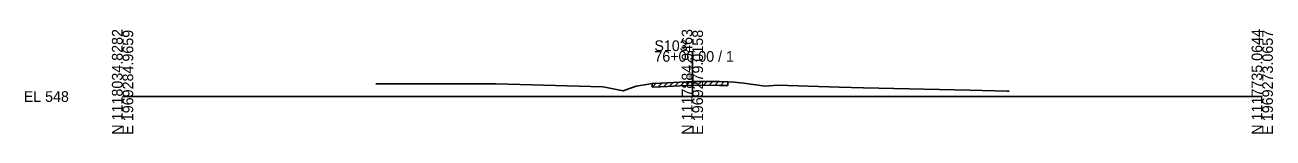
# Model space of a CAD drawing. Extents: x 974 to 1303, y 990 to 14518.
# Drawn here: x 974.3 to 1302.8, y 14490.3 to 14517.6 of the extents above; entities that cross this region are included whole.
import ezdxf

# ---------------------------------------------------------------- set-up
doc = ezdxf.new("R2010")
doc.units = 0
for name, color, linetype in [('Level 10', 7, 'Continuous'), ('Level 60', 7, 'Continuous'), ('Level 61', 7, 'Continuous'), ('Level 63', 7, 'Continuous')]:
    doc.layers.add(name, color=color, linetype=linetype)

msp = doc.modelspace()

# ---------------------------------------------------------------- linework, layer by layer
at = {"layer": 'Level 60'}
for p, q in [((1066.68, 14503.37), (1097.98, 14503.36)), ((1097.98, 14503.36), (1098.34, 14503.35)), ((1098.34, 14503.35), (1126.38, 14502.57)), ((1126.38, 14502.57), (1127.39, 14502.37)), ((1127.39, 14502.37), (1131.75, 14501.53)), ((1131.75, 14501.53), (1132.48, 14501.79)), ((1132.48, 14501.79), (1135.16, 14502.71)), ((1135.16, 14502.71), (1138.41, 14503.27)), ((1138.41, 14503.27), (1139.38, 14503.43)), ((1139.38, 14503.43), (1141.69, 14503.54)), ((1141.69, 14503.54), (1150.03, 14503.97)), ((1150.03, 14503.97), (1157.17, 14503.92)), ((1157.17, 14503.92), (1159.36, 14503.9)), ((1159.36, 14503.9), (1161.21, 14503.76)), ((1161.21, 14503.76), (1161.76, 14503.72)), ((1161.76, 14503.72), (1163.5, 14503.48)), ((1163.5, 14503.48), (1169.11, 14502.68)), ((1169.11, 14502.68), (1170.23, 14502.78)), ((1170.23, 14502.78), (1172.39, 14502.97)), ((1172.39, 14502.97), (1188.65, 14502.48)), ((1188.65, 14502.48), (1195.05, 14502.28)), ((1195.05, 14502.28), (1223.05, 14501.65)), ((1223.05, 14501.65), (1232.82, 14501.38)), ((1232.82, 14501.38), (1233.35, 14501.44))]:
    msp.add_line(p, q, dxfattribs=at)
at = {"layer": 'Level 61'}
for p, q in [((1139.38, 14502.43), (1140.43, 14503.48)), ((1139.38, 14502.43), (1139.38, 14503.43)), ((1139.38, 14502.43), (1141.69, 14502.54)), ((1140.88, 14502.5), (1141.93, 14503.55)), ((1141.69, 14502.54), (1150.03, 14502.97)), ((1142.38, 14502.57), (1143.43, 14503.63)), ((1143.88, 14502.65), (1144.93, 14503.71)), ((1145.38, 14502.73), (1146.43, 14503.79)), ((1146.88, 14502.81), (1147.93, 14503.86)), ((1148.38, 14502.89), (1149.43, 14503.94)), ((1149.88, 14502.97), (1150.88, 14503.97)), ((1150.03, 14502.97), (1157.17, 14502.92)), ((1151.38, 14502.96), (1152.37, 14503.96)), ((1152.88, 14502.95), (1153.87, 14503.95)), ((1154.38, 14502.94), (1155.37, 14503.94)), ((1155.88, 14502.93), (1156.87, 14503.93)), ((1157.17, 14502.92), (1159.36, 14502.9)), ((1157.38, 14502.92), (1158.37, 14503.91)), ((1159.36, 14503.9), (1159.36, 14502.9)), ((1159.36, 14502.9), (1159.36, 14502.9))]:
    msp.add_line(p, q, dxfattribs=at)
at = {"layer": 'Level 63'}
for p, q in [((1150, 14500), (1150, 14511.92)), ((1000, 14500), (1150, 14500)), ((1150, 14500), (1300, 14500))]:
    msp.add_line(p, q, dxfattribs=at)

# ---------------------------------------------------------------- texts
at = {"layer": 'Level 10'}
msp.add_text('551.97', height=0.9, rotation=90, dxfattribs=at).set_placement((1149.95, 14504.47))
at = {"layer": 'Level 63'}
for s, p in [('N 1118034.8282', (1000, 14490)), ('E 1969284.9659', (1002.8, 14490)), ('N 1117884.9463', (1150, 14490)), ('E 1969279.0158', (1152.8, 14490)), ('N 1117735.0644', (1300, 14490)), ('E 1969273.0657', (1302.8, 14490))]:
    msp.add_text(s, height=2.8, rotation=90, dxfattribs=at).set_placement(p)
for s, p in [('S103', (1140, 14511.92)), ('76+00.00 / 1', (1140, 14509.12)), ('EL 548', (974, 14498.6))]:
    msp.add_text(s, height=2.8, dxfattribs=at).set_placement(p)

doc.saveas('drawing.dxf')
